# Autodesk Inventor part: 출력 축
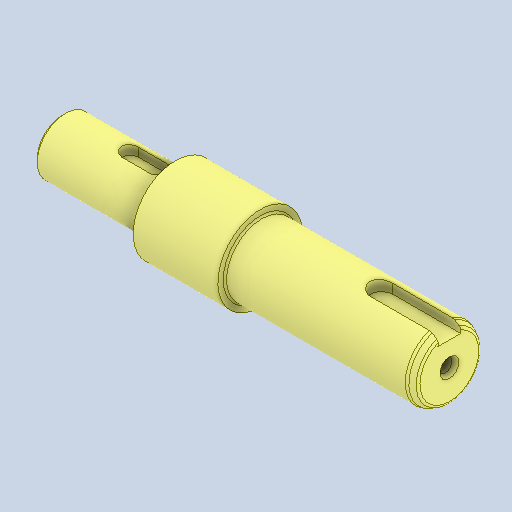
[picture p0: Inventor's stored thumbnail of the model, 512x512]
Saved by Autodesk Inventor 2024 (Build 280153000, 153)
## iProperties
Created: 2025-11
Part Number: 출력 축
Material: 강철, 탄소
Document SubType Name: Modeling
Designer: Eud07
Density: 7.85 g/cm^3
Appearance: 기본값
Author: jhkim
Sending System: Autodesk Inventor 2026
Preprocessor: ST-DEVELOPER v20.1
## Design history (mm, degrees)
node "출력 축1"
node "솔리드2"
node "솔리드1"
